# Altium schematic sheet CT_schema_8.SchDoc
size 403 x 220 mm
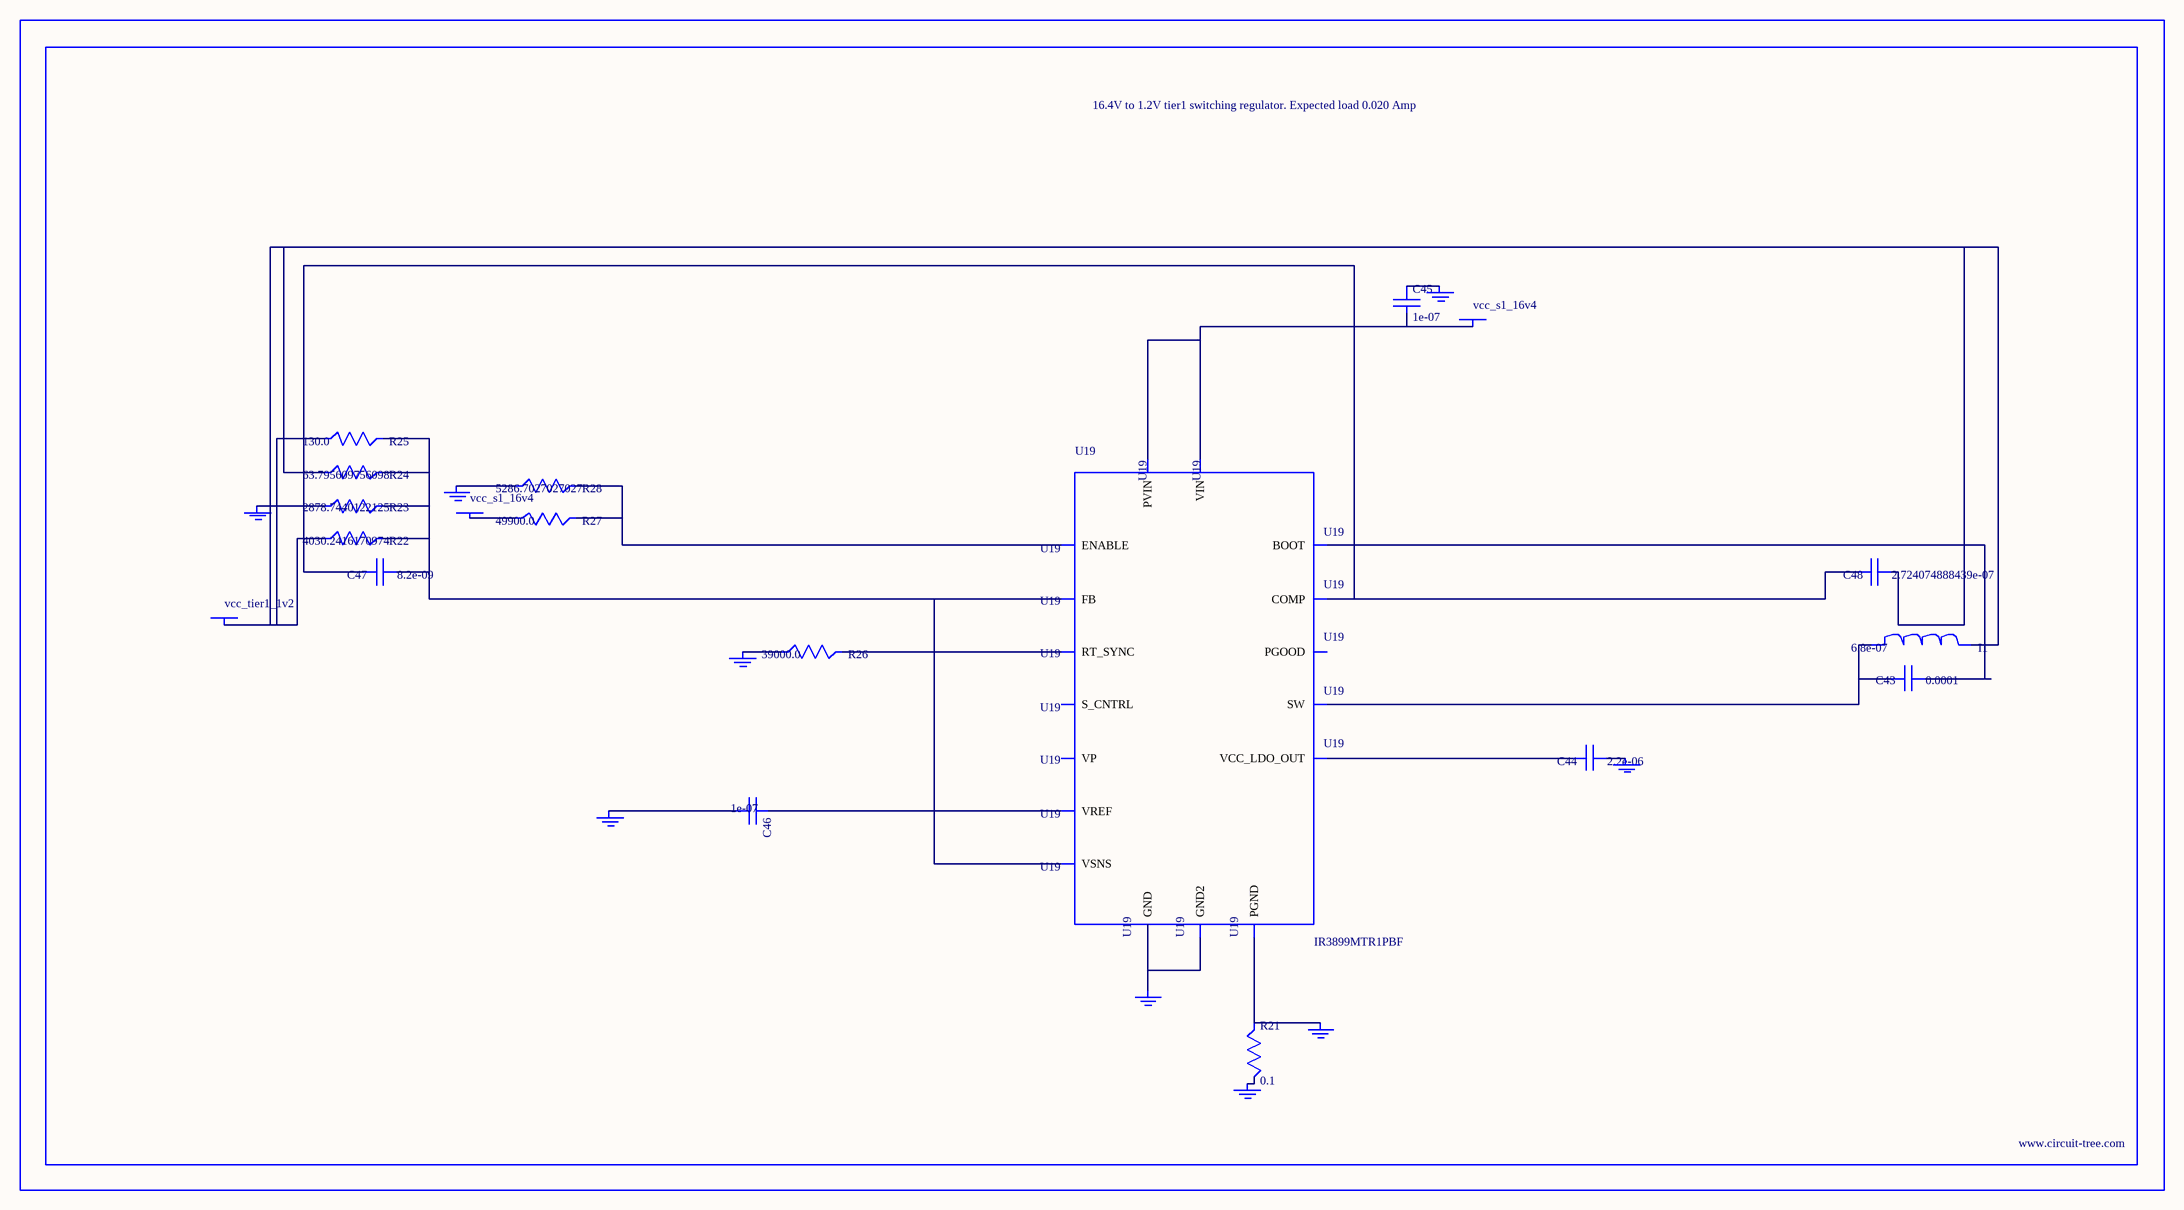
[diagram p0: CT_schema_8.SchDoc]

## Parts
BORDER7  (no value)
C43  0.0001  [C1210]
C44  2.2e-06  [C0603]
C45  1e-07  [C0402]
C46  1e-07  [C0402]
C47  8.2e-09  [C0402]
C48  2.724074888439e-07  [R0603]
GND_INSTANCE_7_0  (no value)
GND_INSTANCE_7_1  (no value)
GND_INSTANCE_7_2  (no value)
GND_INSTANCE_7_3  (no value)
GND_INSTANCE_7_4  (no value)
GND_INSTANCE_7_5  (no value)
GND_INSTANCE_7_6  (no value)
GND_INSTANCE_7_7  (no value)
GND_INSTANCE_7_8  (no value)
I1  6.8e-07  [IND25X25CZ]
POWER_INSTANCE_7_0  vcc_s1_16v4
POWER_INSTANCE_7_1  vcc_s1_16v4
POWER_INSTANCE_7_2  vcc_tier1_1v2
R21  0.1  [R0603]
R22  4030.2416170974  [R0603]
R23  2878.7440122125  [R0603]
R24  63.795609756098  [R0603]
R25  130.0  [R0603]
R26  39000.0  [R0603]
R27  49900.0  [R0603]
R28  5286.7027027027  [R0603]
U19  IR3899MTR1PBF  [IR3899MTR1PBF]

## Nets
NetC43_1: C43.1 U19.14(BOOT)
NetC43_2: C43.2 I1.1 U19.12(SW)
NetC44_1: C44.1 GND_INSTANCE_7_4.0(GND)
NetC44_2: C44.2 U19.10(VCC_LDO_OUT)
NetC45_1: C45.1 GND_INSTANCE_7_3.0(GND)
NetC45_2: C45.2 POWER_INSTANCE_7_0.0(PWR) U19.9(VIN) U19.13(PVIN)
NetC46_1: C46.1 U19.2(VREF)
NetC46_2: C46.2 GND_INSTANCE_7_1.0(GND)
NetC47_1: C47.1 R22.2 R23.2 R24.2 R25.2 U19.1(FB) U19.8(VSNS)
NetC47_2: C47.2 C48.2 U19.3(COMP)
NetC48_1: C48.1 I1.2 POWER_INSTANCE_7_2.0(PWR) R22.1 R24.1 R25.1
NetGND_INSTANCE_7_0_0: GND_INSTANCE_7_0.0(GND) R23.1
NetGND_INSTANCE_7_2_0: GND_INSTANCE_7_2.0(GND) R26.1
NetGND_INSTANCE_7_5_0: GND_INSTANCE_7_5.0(GND) R21.2
NetGND_INSTANCE_7_6_0: GND_INSTANCE_7_6.0(GND) R21.1 U19.11(PGND)
NetGND_INSTANCE_7_7_0: GND_INSTANCE_7_7.0(GND) R28.1
NetGND_INSTANCE_7_8_0: GND_INSTANCE_7_8.0(GND) U19.4(GND) U19.17(GND2)
NetPOWER_INSTANCE_7_1_0: POWER_INSTANCE_7_1.0(PWR) R27.1
NetR26_2: R26.2 U19.5(RT_SYNC)
NetR27_2: R27.2 R28.2 U19.15(ENABLE)

Not connected (* = marked no-connect by the designer): U19 6(S_CNTRL) 7(PGOOD) 16(VP)

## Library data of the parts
BORDER7 = BORDER_PAGE7
C43 = GRM32ER61A107ME20L
C44 = C0603C225K8RACTU
C45 C46 = C0402C104K3RACTU
C47 = C0402C822K3RAC
C48 = C48
GND_INSTANCE_7_0-GND_INSTANCE_7_8 = GND
I1 = IHLP2525CZERR68M01
POWER_INSTANCE_7_0-POWER_INSTANCE_7_2 = PWR
R21 = ERJ-3RSFR10V
R22 = R22
R23 = R23
R24 = R24
R25 = RC0603JR-07130RL
R26 = RC0603JR-0739KL
R27 = RC0603FR-0749K9
R28 = R28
